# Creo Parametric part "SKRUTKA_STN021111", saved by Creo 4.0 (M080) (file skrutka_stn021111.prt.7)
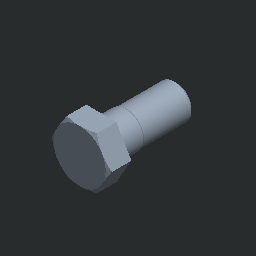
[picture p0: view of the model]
Units: Custom; MM, KILOGRAM, SECS
Materials in the file: OCEL, OCEL_N

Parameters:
  PTC_MATERIAL_NAME = "OCEL"
  NAZOV = "SKRUTKA_STN021111"
  NORMA = "STN 02 1111"

Other parameters: HMOTNOST, HUSTOTA, D10, D25, D23, D15

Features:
  1. datum plane "DTM1"
  2. protrusion
  3. datum plane "DTM2"
  4. cut
  5. cut
  6. cut
  7. chamfer
  8. datum plane "DTM3"
  9. datum plane "DTM4"

Other named items: BLIND

Layers: 1, 2, 3, 4, 5, 6, 7, 8, 9, 10, 11, 12, 13, 14, 15, 16, 17, 18, 19, 20, 21, 22, 23, 24, 25, 26, 27, 28, 29, 30, 31, 32

Family table entries: GENERIC, SKRUTKA_M10, SKRUTKA_STN021111, value(d_val), 2/&, 2/0, value(i_val), SKRUTKA_M12, SKRUTKA_STN021111, !/(, 2/*, 2/ , 2/2, SKRUTKA_M14, SKRUTKA_STN021111, !/,, 2/., 2/", 2/5, SKRUTKA_M16, SKRUTKA_STN021111, !/0, 2/1, 2/$, 2/8, SKRUTKA_M18, SKRUTKA_STN021111, !/2, 2/3, 2/(, 2/;, SKRUTKA_M20, SKRUTKA_STN021111, !/4, 2/5, 2/*, 2/>, SKRUTKA_M22, SKRUTKA_STN021111, !/6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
